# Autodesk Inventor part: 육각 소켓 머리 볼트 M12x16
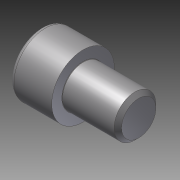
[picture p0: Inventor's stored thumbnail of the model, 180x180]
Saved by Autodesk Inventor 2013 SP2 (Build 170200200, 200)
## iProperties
Created: 2024-07
Part Number: 육각 소켓 머리 볼트 M12x16
Material: Generic
Document SubType Name: Modeling
Designer: 601
Density: 1 g/cm^3
Author: 601
변환 표준: STEP AP214IS
전처리기: Build: 200, Release: 2013 SP2 Update 6 - Date: Thu 07/17/2014
전송 단위: 밀리미터
불확실성: 0.01
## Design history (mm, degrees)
node "육각 소켓 머리 볼트 M12x161"
body "Solid1"
node "기준1"
